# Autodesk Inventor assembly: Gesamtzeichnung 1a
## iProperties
Created: 2005-12
Part Number: Gesamtzeichnung 1a
Document SubType Name: Assembly
Designer: Sascha
Manufacturer: Standard
Standards Organization: Custom
Author: Sascha
